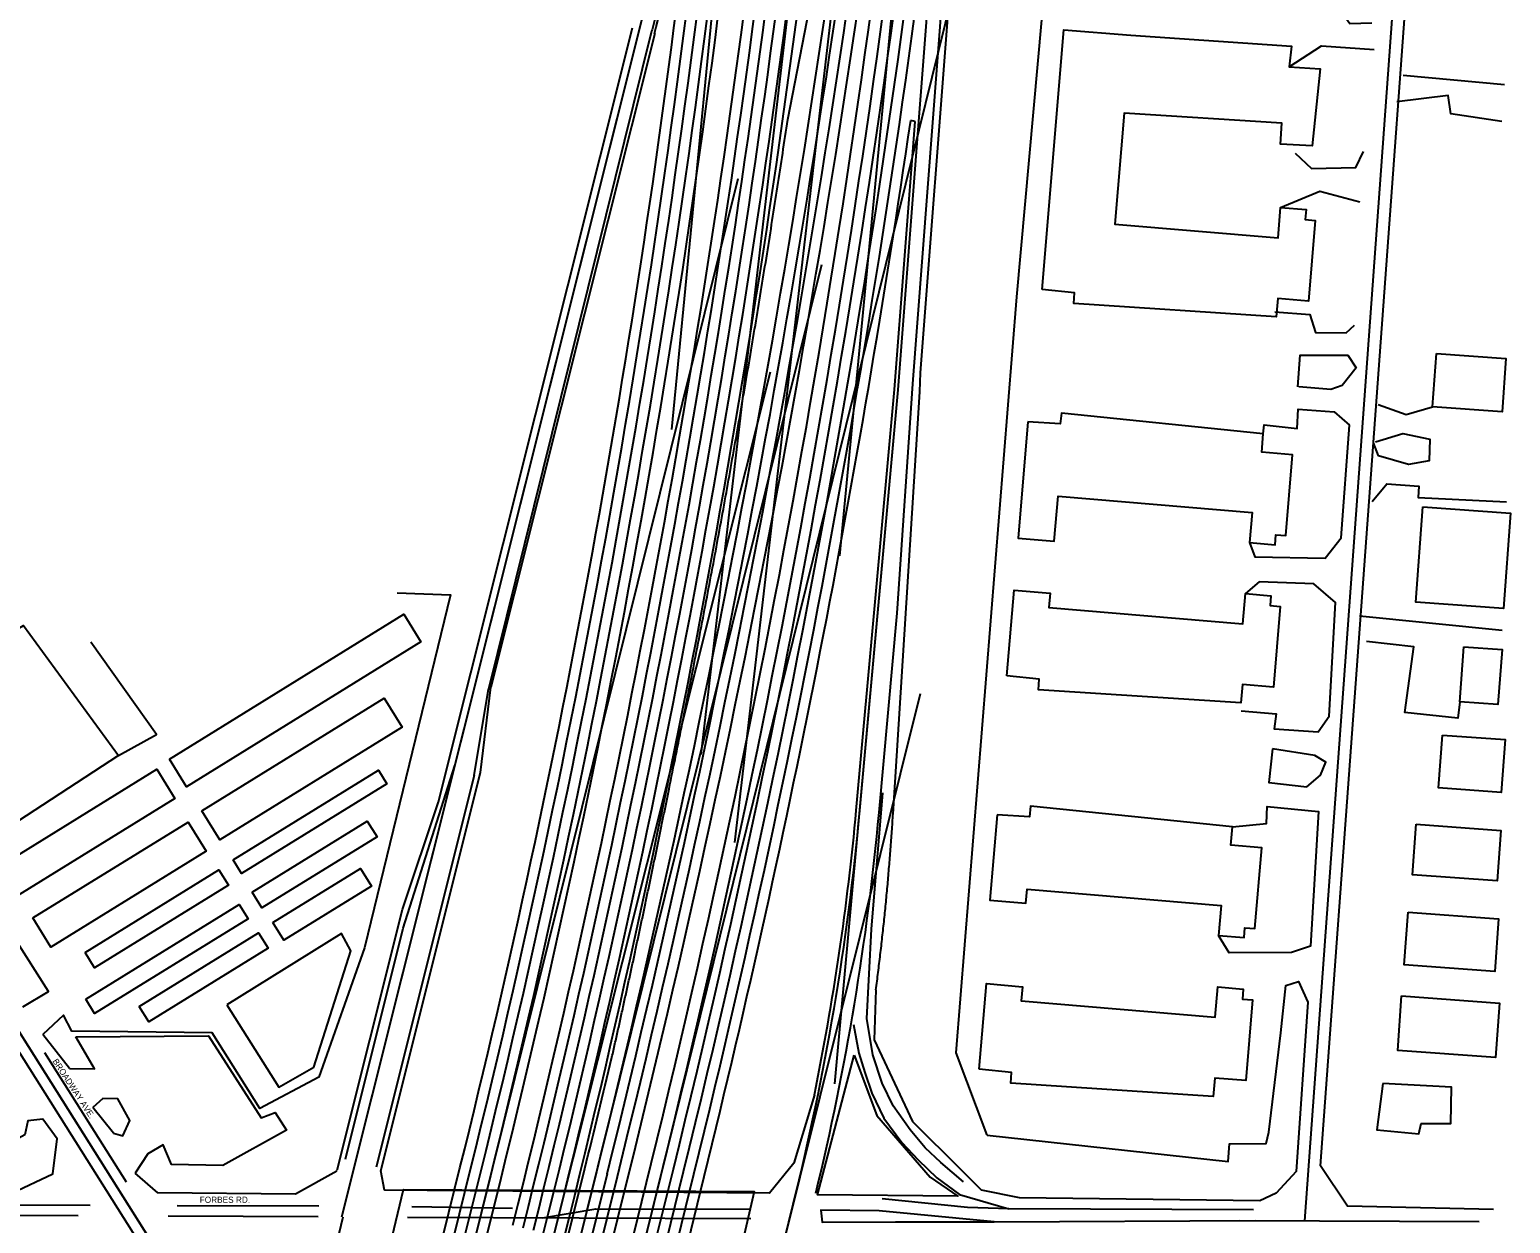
# Model space of a CAD drawing. Extents: x 227157 to 233208, y 434992 to 456232.
# Drawn here: x 228046 to 229727, y 445587 to 446942 of the extents above; entities that cross this region are included whole.
import ezdxf

# ---------------------------------------------------------------- set-up
doc = ezdxf.new("R2010")
doc.units = 0
for name, color, linetype in [('BD_X_Building', 7, 'Continuous'), ('BR_X_Slab_Object', 7, 'Continuous'), ('Default', 7, 'Continuous'), ('GE_X_Alignment', 7, 'Continuous'), ('PM_X_Edge_Line', 7, 'Continuous'), ('PM_X_Lane_Line', 7, 'Continuous'), ('PV_X_EOP', 7, 'Continuous'), ('SV_X_Text_Name', 7, 'Continuous')]:
    doc.layers.add(name, color=color, linetype=linetype)

msp = doc.modelspace()

# ---------------------------------------------------------------- linework, layer by layer
at = {"layer": 'BD_X_Building'}
for points in [[(229195.7, 446647), (229220.5, 446942.1), (229296.5, 446935.7), (229479, 446923.3), (229476.2, 446900), (229511.4, 446897.5), (229502.3, 446810.1), (229466.4, 446812.2), (229468.1, 446836), (229289.1, 446847.2), (229278.5, 446721.5), (229463.7, 446706), (229466.6, 446740.3), (229495.6, 446737.8), (229494.6, 446726.5), (229505.9, 446725.6), (229498.2, 446633.9), (229463.3, 446636.8), (229461.5, 446616), (229231.6, 446631.1), (229232.4, 446643.2)], [(229643.5, 446574.6), (229722.4, 446568.9), (229718, 446508.4), (229639.1, 446514.1)], [(229179.7, 446497), (229168.6, 446364.9), (229209.5, 446361.5), (229213.8, 446412.7), (229434.1, 446394.2), (229431.2, 446359.8), (229460.2, 446357.4), (229461.1, 446368.7), (229472.4, 446367.8), (229480.1, 446459.4), (229445.1, 446462.4), (229446.9, 446483.2), (229217.7, 446506.7), (229216.4, 446494.6)], [(229627.9, 446400.5), (229727.5, 446393.2), (229719.6, 446285.1), (229620, 446292.4)], [(229155.7, 446208.7), (229163.9, 446305.8), (229204.8, 446302.3), (229203.4, 446286.2), (229423.8, 446267.7), (229426.6, 446302), (229455.6, 446299.6), (229454.6, 446288.3), (229466, 446287.3), (229458.3, 446195.7), (229423.3, 446198.6), (229421.5, 446177.8), (229191.6, 446192.8), (229192.4, 446205)], [(228204.8, 446114.2), (228471.1, 446278.5), (228490.4, 446247.1), (228224.2, 446082.8)], [(229674.8, 446241.7), (229718, 446238.6), (229713.4, 446175.9), (229670.2, 446179)], [(228241.6, 446055.4), (228448.8, 446183.2), (228469.1, 446150.3), (228261.9, 446022.5)], [(229650.3, 446141.3), (229721.4, 446136.2), (229717, 446076.2), (229645.9, 446081.4)], [(228012.2, 445992.6), (228190.5, 446102.5), (228211, 446069.2), (228032.8, 445959.3)], [(228277.3, 445999.7), (228442.2, 446101.4), (228451.7, 446085.9), (228286.8, 445984.2)], [(229144.6, 446051), (229136.5, 445953.9), (229177.4, 445950.5), (229178.7, 445966.6), (229399.1, 445948.1), (229396.2, 445913.8), (229425.1, 445911.4), (229426.1, 445922.7), (229437.4, 445921.7), (229445.1, 446013.4), (229410.1, 446016.3), (229411.9, 446037.2), (229182.6, 446060.6), (229181.4, 446048.5)], [(228049.8, 445933.8), (228226.2, 446042.6), (228246.6, 446009.5), (228070.2, 445900.7)], [(228298.9, 445963.2), (228429.5, 446043.8), (228440.5, 446025.9), (228309.9, 445945.4)], [(229620.5, 446040.2), (229716.8, 446033.2), (229712.6, 445975.8), (229616.3, 445982.9)], [(228109, 445894.6), (228261, 445988.3), (228271.7, 445971.1), (228119.7, 445877.3)], [(228322.2, 445928.6), (228421.9, 445990.1), (228434.4, 445969.9), (228334.7, 445908.4)], [(228109.7, 445841.6), (228284.1, 445949.2), (228294.1, 445932.9), (228119.7, 445825.3)], [(229611.4, 445940.2), (229714, 445932.7), (229709.7, 445873), (229607, 445880.5)], [(228170.6, 445833.4), (228306.1, 445917), (228317, 445899.4), (228181.4, 445815.8)], [(228270, 445835.1), (228328.9, 445741.8), (228368.8, 445764.4), (228410.6, 445896.4), (228400, 445916.1)], [(229124.4, 445762.1), (229132.5, 445859.2), (229173.4, 445855.7), (229172.1, 445839.6), (229392.4, 445821.1), (229395.3, 445855.4), (229424.2, 445853), (229423.3, 445841.7), (229434.6, 445840.7), (229426.9, 445749.1), (229391.9, 445752), (229390.1, 445731.2), (229160.2, 445746.2), (229161, 445758.4)], [(229604, 445845.2), (229715.2, 445837.1), (229710.7, 445775.3), (229599.5, 445783.4)], [(229582.8, 445746), (229575.7, 445693.2), (229623.4, 445688.9), (229626.3, 445700.3), (229659.8, 445700.3), (229660.5, 445741.7)]]:
    msp.add_lwpolyline(points, close=True, dxfattribs=at)
at = {"layer": 'BR_X_Slab_Object'}
msp.add_lwpolyline([(228457.7, 445571.8), (228470.5, 445625.7), (228868.7, 445623.1), (228856.1, 445569.3)], close=True, dxfattribs=at)
at = {"layer": 'Default'}
for points in [[(228782.8, 447061.6), (228782.3, 447059.6), (228781.3, 447055.5), (228779.9, 447049.3), (228778.4, 447043.2), (228776.9, 447037), (228775.4, 447030.8), (228773.9, 447024.7), (228772.4, 447018.5), (228770.9, 447012.4), (228769.4, 447006.3), (228767.8, 447000.1), (228766.3, 446994), (228764.7, 446987.8), (228763.2, 446981.7), (228761.6, 446975.6), (228760, 446969.4), (228758.4, 446963.3), (228756.8, 446957.2), (228755.2, 446951.1), (228753.6, 446945), (228752.5, 446940.9), (228751.9, 446938.8)], [(228772.2, 446080.5), (228774.7, 446093.1), (228779.9, 446118.3), (228787.6, 446156.1), (228795.1, 446193.9), (228802.5, 446231.8), (228809.8, 446269.7), (228817.1, 446307.6), (228824.2, 446345.5), (228831.2, 446383.4), (228838.1, 446421.4), (228844.8, 446459.3), (228851.5, 446497.3), (228858.1, 446535.3), (228864.6, 446573.4), (228870.9, 446611.4), (228877.2, 446649.5), (228883.4, 446687.5), (228889.4, 446725.6), (228895.3, 446763.7), (228901.2, 446801.9), (228905, 446827.3), (228906.9, 446840)], [(228707.3, 445775.6), (228708.4, 445780.7), (228710.7, 445790.8), (228714.1, 445806), (228717.4, 445821.3), (228720.8, 445836.5), (228724.1, 445851.7), (228727.5, 445866.9), (228730.8, 445882.2), (228734.1, 445897.4), (228737.3, 445912.6), (228740.6, 445927.9), (228743.8, 445943.1), (228747, 445958.4), (228750.2, 445973.6), (228753.4, 445988.9), (228756.6, 446004.2), (228759.7, 446019.4), (228762.9, 446034.7), (228766, 446050), (228769.1, 446065.2), (228771.1, 446075.4), (228772.2, 446080.5)], [(229007.1, 445852.1), (229007.5, 445855.4), (229008.4, 445862.1), (229009.6, 445872), (229010.8, 445882), (229012, 445892), (229013.2, 445902), (229014.3, 445912), (229015.4, 445922), (229016.5, 445932), (229017.5, 445942), (229018.5, 445952), (229019.4, 445962), (229020.4, 445972), (229021.2, 445982), (229022.1, 445992), (229022.9, 446002), (229023.7, 446012), (229024.5, 446022.1), (229025.2, 446032.1), (229025.9, 446042.1), (229026.3, 446048.8), (229026.5, 446052.1)]]:
    msp.add_open_spline(points, degree=3, dxfattribs=at)
at = {"layer": 'GE_X_Alignment'}
for p, q in [((228965.9, 446344.9), (229248.4, 449290.1)), ((229216.7, 449201.7), (228846.5, 446019.3)), ((228808.5, 446119.2), (229047.2, 448160.1)), ((228062.6, 442805), (229317.7, 447888.8)), ((229494.2, 445590.1), (229614.4, 447248.6)), ((228348.7, 444751.1), (228850.5, 446773.2)), ((227958.1, 442696), (228945.6, 446675.5)), ((227973.9, 442912.3), (228887.3, 446553.8)), ((228960.4, 445745.4), (229032.3, 446533.2)), ((227769.3, 446224), (229002.6, 444269.9)), ((228576.1, 444256.1), (229057.6, 446188.4))]:
    msp.add_line(p, q, dxfattribs=at)
for centre, radius, start, end in [((216659.5, 448640.3), 12469.3, 346.13224, 354.52202), ((215266.9, 448976.9), 13830.3, 346.06427, 353.36515), ((217439.7, 448403.1), 11467.5, 346.0642, 354.46771), ((216725.3, 448562.4), 12285.2, 345.91876, 353.32977), ((226043.3, 446324.1), 2957.6, 346.008, 354.7906)]:
    msp.add_arc(centre, radius, start, end, dxfattribs=at)
at = {"layer": 'PM_X_Edge_Line'}
for p, q in [((228775.3, 446488.1), (229015, 448962.1)), ((228400.6, 445594.6), (228838, 447339.9)), ((229032.3, 446533.2), (229089.3, 447276.3)), ((229048.8, 446539.9), (229105.2, 447274.9)), ((228400.6, 445594.6), (228738.4, 446942.2)), ((228751.9, 446938.8), (228567.2, 446193.4)), ((228751.9, 446938.8), (228751.9, 446938.8)), ((228988.7, 446055.6), (229032.3, 446533.2)), ((229031.3, 446279.8), (229048.8, 446539.9)), ((229010.6, 446053.6), (229031.3, 446279.8)), ((228568.1, 444958.3), (227769.3, 446224)), ((228550.9, 446095.4), (228567.2, 446193.4)), ((228470.3, 445922), (228529, 446106.9)), ((228550.9, 446095.4), (228439.5, 445650.8)), ((228404.6, 445659.9), (228470.3, 445922)), ((228361.2, 444014.4), (228765.4, 445651.6)), ((228294, 444049.5), (228690.2, 445646.1)), ((228317.3, 444043.7), (228713.5, 445640.3)), ((228325.4, 444756.9), (228546.3, 445647.1)), ((228348.7, 444751.1), (228569.6, 445641.3)), ((228396.1, 444005.7), (228800.3, 445643)), ((227295.9, 445599.2), (228101.3, 445595.9)), ((228480.1, 445606.2), (228594.5, 445604.3)), ((228576.1, 444256.1), (228913.2, 445609)), ((229435.9, 445602.4), (229157.9, 445603.5)), ((228203.2, 445595.5), (228373.7, 445594.8)), ((228346.9, 445370.3), (228402.2, 445594.6)), ((228475.2, 445594.3), (228865, 445592.7)), ((229420.2, 445590.4), (229692.1, 445589.3))]:
    msp.add_line(p, q, dxfattribs=at)
for points in [[(229106.3, 445634.4), (229080.7, 445656.1), (229063.1, 445672.7), (229045.8, 445693.1), (229026.8, 445720.4), (229014.1, 445746.1), (229003.7, 445778.5), (228996.7, 445819.5), (229002, 445921), (229015, 446075.9)], [(228981.6, 445813), (228987.6, 445780.4), (228994.6, 445758.4), (229002.5, 445734.8), (229016.2, 445706.6), (229036.5, 445678.9), (229054.9, 445659.3), (229076.3, 445638.8), (229101.8, 445619.8), (229157.9, 445603.5)], [(228628.6, 445593.5), (228688.9, 445603.6), (228863.6, 445603.1)], [(229141.4, 445588.9), (229010.7, 445601.3), (228944.4, 445601.9), (228945.8, 445588.6), (229029.1, 445589), (229141.4, 445588.9), (229437.6, 445590.5)], [(229157.9, 445603.5), (229111.2, 445605.1), (229014, 445615)]]:
    msp.add_lwpolyline(points, dxfattribs=at)
for centre, radius, start, end in [((216659.5, 448640.3), 12469.3, 346.13224, 354.52202), ((215266.9, 448976.9), 13830.3, 346.06427, 353.36515), ((215266.9, 448976.9), 13854.3, 346.06427, 353.36515), ((217439.7, 448403.1), 11443.5, 346.0642, 354.46771), ((217439.7, 448403.1), 11467.5, 346.0642, 354.46771), ((216659.5, 448640.3), 12505.3, 346.13224, 353.55332), ((216725.3, 448562.4), 12249.2, 345.91876, 353.32977), ((216725.3, 448562.4), 12285.2, 345.91876, 353.32977), ((226043.3, 446324.1), 2957.6, 346.008, 354.7906), ((226043.3, 446324.1), 2979.6, 346.3549, 354.7906)]:
    msp.add_arc(centre, radius, start, end, dxfattribs=at)
at = {"layer": 'PM_X_Lane_Line'}
for p, q in [((228323.4, 445323.5), (228028.9, 445790.1)), ((228063, 445781.1), (228155.6, 445634.4)), ((228701.8, 445643.2), (228305.7, 444046.6)), ((228337.1, 444754), (228558, 445644.2)), ((228372.8, 444011.5), (228777, 445648.7)), ((228384.5, 444008.6), (228788.7, 445645.9)), ((227924.8, 445608.6), (228114.8, 445607.8)), ((228213.5, 445607.4), (228374.3, 445606.8))]:
    msp.add_line(p, q, dxfattribs=at)
for centre, radius, start, end in [((216659.5, 448640.3), 12481.3, 346.13224, 354.52202), ((216659.5, 448640.3), 12493.3, 346.13224, 354.52202), ((215266.9, 448976.9), 13842.3, 346.06427, 353.36515), ((217439.7, 448403.1), 11455.5, 346.0642, 354.46771), ((216725.3, 448562.4), 12261.2, 345.91876, 353.32977), ((216725.3, 448562.4), 12273.2, 345.91876, 353.32977)]:
    msp.add_arc(centre, radius, start, end, dxfattribs=at)
at = {"layer": 'PV_X_EOP'}
for p, q in [((229057.8, 446552.7), (229113.2, 447274.2)), ((228906.9, 446840), (228948.5, 447052)), ((228510.4, 446065.7), (228730.6, 446944.2)), ((228755.8, 446937.9), (228569.9, 446195.9)), ((229605.7, 446890.5), (229720.8, 446880)), ((229028.3, 446533.6), (229051.6, 446837.8)), ((229051.6, 446837.8), (229046.6, 446839)), ((229056.8, 446531.4), (229057.8, 446552.7)), ((228984.7, 446055.9), (229028.3, 446533.6)), ((229026.5, 446052.1), (229056.8, 446531)), ((229556.2, 446276.7), (229718.1, 446260.6)), ((228557.9, 446098.8), (228569.9, 446195.9)), ((228444.7, 445646.9), (228557.9, 446098.8)), ((228469.5, 445943.3), (228510.4, 446065.7)), ((228395.4, 445647.6), (228469.5, 445943.3)), ((228091.4, 445762.7), (228061.1, 445801.3)), ((228141.1, 445689.5), (228117.8, 445718.7)), ((228280.4, 444052.9), (228676.6, 445649.5)), ((228347.6, 444017.7), (228751.8, 445655)), ((228403.6, 445121.9), (228534.7, 445650)), ((228328.9, 444040.8), (228725.1, 445637.4)), ((228360.3, 444748.2), (228581.3, 445638.4)), ((228407.8, 444002.9), (228812, 445640.1))]:
    msp.add_line(p, q, dxfattribs=at)
for points in [[(229708.3, 445603), (229542.7, 445606.5), (229511.7, 445652.4), (229619.4, 447119.7), (229630.3, 447250.5)], [(229133.5, 445687.3), (229098.1, 445780.7), (229167, 446638.7), (229200.3, 447008), (229528, 446972.8), (229545, 446949.1), (229570.1, 446949.7)], [(229476.2, 446900), (229513.1, 446923.9), (229572.9, 446919.5)], [(229717.7, 446838), (229659.7, 446846.5), (229657, 446867.4), (229598.5, 446860.3)], [(229483, 446802.1), (229501.7, 446784.5), (229551.9, 446785.8), (229560.7, 446804)], [(229466.6, 446740.3), (229511.1, 446758.8), (229556.5, 446746.7)], [(229459.9, 446621.8), (229499.7, 446618.9), (229506.1, 446598.4), (229541.1, 446598), (229550.3, 446606.6)], [(229486.3, 446536.7), (229488.9, 446572.5), (229542.9, 446572.6), (229552.5, 446558.4), (229536.3, 446538.3), (229523.7, 446533.5), (229487.1, 446536.6)], [(229446.9, 446483.2), (229448, 446493.5), (229485.3, 446489.3), (229486.4, 446511.2), (229527.5, 446508.2), (229544.6, 446493.2)], [(229577.5, 446516.8), (229609.3, 446505.4), (229639.1, 446514.1)], [(229431.2, 446359.8), (229437.2, 446343.7), (229517.2, 446342.2), (229535.3, 446365.2), (229544.6, 446493.2)], [(229574.4, 446474.1), (229605.3, 446483.7), (229635.9, 446477.3), (229635.3, 446452.5), (229611.7, 446448.5), (229577.7, 446458.3), (229572, 446473.3)], [(229570.7, 446406.4), (229587.2, 446426.7), (229623.5, 446424), (229622.6, 446411.2), (229723, 446406)], [(229421.6, 446168.9), (229461.7, 446165.3), (229459.4, 446148.6), (229509.1, 446145.2), (229521.6, 446162.8), (229529, 446291.8), (229504.1, 446313), (229442.1, 446315.4), (229426.6, 446302)], [(228463.5, 446302.9), (228524.1, 446300.6), (228426.3, 445900), (228374.6, 445753), (228307.5, 445717.5), (228253.3, 445803.2), (228094.1, 445805.4), (228084.4, 445823.3), (228061.1, 445801.3)], [(227838.4, 446150), (227877.5, 446176.5), (227836.2, 446237.5), (227903.8, 446271.9), (227939.1, 446227.1), (227966, 446223.7), (228039.2, 446265.6), (228147.1, 446118.2), (227965.4, 445999.9), (227979.6, 445988.1)], [(228147.1, 446118.2), (228190.2, 446141.9), (228115.7, 446246.8)], [(229670.2, 446179), (229667.9, 446160.5), (229607.6, 446167.1), (229618, 446241.4), (229564.1, 446247.5)], [(229411.9, 446037.2), (229450.5, 446041.1), (229451.2, 446060.4), (229509.4, 446054.7), (229500.4, 445901.6), (229479.1, 445894.6), (229408.3, 445894), (229396.2, 445913.8)], [(228038.3, 445832.9), (228067.4, 445850.1), (227979.6, 445988.1), (227954, 445961.3)], [(229007.1, 445852.1), (229005, 445795.4), (229048.5, 445702.7), (229103.7, 445648), (229126.8, 445624.6)], [(229133.5, 445687.3), (229407, 445657.4), (229408.5, 445677.3), (229450, 445677.8), (229453, 445690.5), (229467, 445803.2), (229472.4, 445857.2), (229487, 445861.8), (229497.4, 445838.2), (229484.1, 445646), (229461.6, 445621.2), (229443.1, 445612.5)], [(228091.4, 445762.7), (228119.6, 445762.5), (228098.6, 445798.9)], [(228098.6, 445798.9), (228249, 445799.8), (228308.9, 445706.7), (228324.7, 445712.8), (228337.7, 445692.7), (228265.5, 445652.8), (228207.2, 445653.8), (228197.6, 445676.2), (228180.1, 445666.1), (228165.9, 445644.2)], [(228141.1, 445689.5), (228151.9, 445686.6), (228159.7, 445704), (228146.1, 445728.3), (228129.3, 445728.9), (228117.8, 445718.7)], [(228937.2, 445732.9), (228913.9, 445655.6), (228886, 445621.3), (228449.1, 445624.6), (228444.7, 445646.9)], [(228395, 445646.5), (228347.8, 445620.1), (228191.8, 445621.6), (228165.9, 445644.2)], [(229443.1, 445612.5), (229169.9, 445615.9), (229126.8, 445624.6)]]:
    msp.add_lwpolyline(points, dxfattribs=at)
for points in [[(229457.4, 446125.8), (229453.2, 446087.4), (229496.4, 446082.8), (229511.7, 446096), (229517.8, 446110.6), (229505.4, 446118)], [(228982.4, 445777.9), (229008.1, 445709.4), (229068.8, 445639.5), (229099.9, 445618), (228940.6, 445619.4)], [(227927.3, 445623.4), (228025.8, 445621.2), (228072.5, 445643.5), (228077.5, 445683.2), (228061.2, 445705.2), (228044, 445703.6), (228040.7, 445687.6), (227990, 445659.6), (227940.4, 445655.3), (227912.2, 445651)]]:
    msp.add_lwpolyline(points, close=True, dxfattribs=at)
for centre, radius, start, end in [((216659.5, 448640.3), 12455.3, 346.13224, 354.52202), ((215266.9, 448976.9), 13866.3, 346.06427, 353.36515), ((217439.7, 448403.1), 11479.5, 346.0642, 354.46771), ((216725.3, 448562.4), 12237.2, 345.91876, 353.32977), ((216725.3, 448562.4), 12297.2, 345.91876, 353.32977), ((217439.7, 448403.1), 11431.5, 346.0642, 353.22696), ((224757.4, 447939.9), 4122, 345.9309, 347.6317), ((216659.5, 448640.3), 12517.3, 346.13224, 351.72618), ((226043.3, 446324.1), 2953.6, 348.4537, 354.7906), ((215266.9, 448976.9), 13816.3, 346.06427, 346.60311)]:
    msp.add_arc(centre, radius, start, end, dxfattribs=at)

# ---------------------------------------------------------------- texts
at = {"layer": 'SV_X_Text_Name'}
msp.add_text('BROADWAY AVE.', height=7, rotation=303.1362, dxfattribs=at).set_placement((228071.7, 445771.1))
msp.add_text('FORBES RD.', height=7, dxfattribs=at).set_placement((228239.2, 445610.4))

doc.saveas('drawing.dxf')
